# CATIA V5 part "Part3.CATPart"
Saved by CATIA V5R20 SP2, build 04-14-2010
Part number: Part3
Bounding box of the stored display mesh (mm): x 0 to 20, y 285.554 to 936.874, z -176.125 to -134.225
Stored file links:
  E:\CATIA\New folder\Part3.CATPart
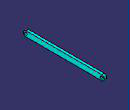
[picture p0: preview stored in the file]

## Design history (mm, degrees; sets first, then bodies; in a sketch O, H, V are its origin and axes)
Body1 (main body)
  Sketch1 on yz-plane, origin (0, 0, 0), H (0, 1, 0), V (0, 0, 1)
    construction line L1 (306.4937, -155.1748) -> (915.9337, -155.1748)
    line L2 (306.4937, -134.2248) -> (915.9337, -134.2248)
    line L3 (915.9337, -176.1248) -> (306.4937, -176.1248)
    arc A1 centre (915.9337, -155.1748) radius 20.95 from (915.9337, -134.2248) to (915.9337, -176.1248) cw
    arc A2 centre (306.4937, -155.1748) radius 20.95 from (306.4937, -176.1248) to (306.4937, -134.2248) cw
    circle A3 centre (915.9337, -155.1748) radius 11.04
    circle A4 centre (306.4937, -155.1748) radius 11.04
  Pad1: profile Sketch1, direction (1, 0, 0), length 20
